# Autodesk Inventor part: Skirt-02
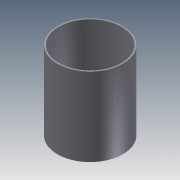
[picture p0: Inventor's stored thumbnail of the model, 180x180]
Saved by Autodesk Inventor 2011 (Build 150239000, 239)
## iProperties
Created: 2010-06
Part Number: Skirt-02
Document SubType Name: Modeling
Designer: mklassen
Density: 1 g/cm^3
OD: 24.000 in
THK: 0.500 in
LEN: 2.500 ft
SKVOFS: 6.000 in
Author: mklassen
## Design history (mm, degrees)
sketch "skSkirt"
  geometry: C1 r 317.5 at (0, 0); C2 r 304.8 at (0, 0); 1 further point
  constraints: 2 centre point, 1 coincident
  dimensions: "d0" = 609.6 diameter of C2 (derived); "d1" = 12.7 radial gap between concentric circles of C1 C2 (derived)
extrude "Extrusion1" new body sketch "skSkirt" stored distance "d2" = 762 (derived); taper "d3" = 0 deg
body "Solid1"
other parameters: "d4" = 152.4 (derived), "d5" = 0
